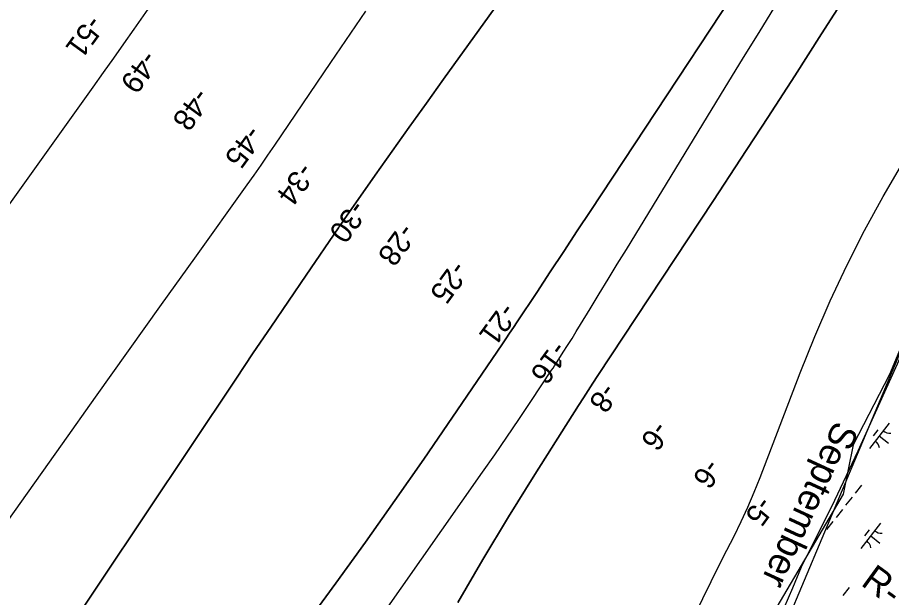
# Model space of a CAD drawing. Extents: x 3896831 to 3918110, y 171006 to 193349.
# Drawn here: x 3907446 to 3908805, y 178993 to 179895 of the extents above; entities that cross this region are included whole.
import ezdxf

# ---------------------------------------------------------------- set-up
doc = ezdxf.new("R2010")
doc.units = 0
for name, color, linetype in [('V-RIVR-EDGE', 7, 'Continuous'), ('V-RIVR-IDEN', 7, 'Continuous'), ('V-RIVR-RANG', 7, 'Continuous'), ('V-RIVR-RANG-IDEN', 7, 'Continuous'), ('V-RRAP-FSHR', 7, 'Continuous'), ('V-TOPO-DPTH', 7, 'Continuous'), ('V-TOPO-MAJR', 7, 'Continuous'), ('V-TOPO-MINR', 7, 'Continuous'), ('V-WETL-SWMP', 7, 'Continuous')]:
    doc.layers.add(name, color=color, linetype=linetype)

msp = doc.modelspace()

# ---------------------------------------------------------------- linework, layer by layer
at = {"layer": 'V-RIVR-EDGE'}
msp.add_lwpolyline([(3908875.5, 179514.5), (3908802.2, 179339.6), (3908745.8, 179230.1), (3908730, 179153.3), (3908572, 178884.7), (3908505.4, 178750.4), (3908358.7, 178539.4), (3908245.8, 178389.3), (3908234.5, 178346.4), (3908226.6, 178313.7), (3908205.2, 178288.9), (3908181.5, 178273.1), (3908140.8, 178198.6), (3908014.4, 177963.8)], dxfattribs=at)
at = {"layer": 'V-RRAP-FSHR'}
msp.add_lwpolyline([(3910095.3, 181395.6), (3909257.3, 180118.1), (3908889.4, 179541.5), (3908614.7, 178888.4), (3907991.9, 177840.9), (3908307, 176956.6)], dxfattribs=at)
at = {"layer": 'V-TOPO-DPTH'}
for points in [[(3907701.3, 178701.9), (3907713.1, 178714.3), (3907715.7, 178717), (3907732.5, 178735.7), (3907748.8, 178754.8), (3907764.5, 178774.4), (3907779.6, 178794.5), (3907940.9, 179015), (3907987.1, 179078.9), (3908032.9, 179143.2), (3908078, 179207.9), (3908122.6, 179272.9), (3908199.2, 179385.8), (3908205.2, 179394.7), (3908211.2, 179403.6), (3908217.1, 179412.5), (3908223.1, 179421.4), (3908253.4, 179467.2), (3908274.5, 179499), (3908295.6, 179530.8), (3908316.6, 179562.6), (3908337.6, 179594.5), (3908658.6, 180081.4)], [(3908658.6, 180081.4), (3908337.6, 179594.5), (3908316.6, 179562.6), (3908295.6, 179530.8), (3908274.5, 179499), (3908253.4, 179467.2), (3908223.1, 179421.4), (3908217.1, 179412.5), (3908211.2, 179403.6), (3908205.2, 179394.7), (3908199.2, 179385.8), (3908122.6, 179272.9), (3908078, 179207.9), (3908032.9, 179143.2), (3907987.1, 179078.9), (3907940.9, 179015), (3907779.6, 178794.5), (3907764.5, 178774.4), (3907748.8, 178754.8), (3907732.5, 178735.7), (3907715.7, 178717), (3907713.1, 178714.3), (3907701.3, 178701.9)], [(3907459.1, 178850.4), (3907501.4, 178908), (3907503.3, 178910.7), (3907505.2, 178913.4), (3907785.4, 179332.4), (3907812.6, 179372.9), (3907839.8, 179413.2), (3907867.2, 179453.5), (3907894.6, 179493.8), (3907945.2, 179567.6), (3907947.4, 179570.9), (3907949.7, 179574.2), (3907952, 179577.4), (3907954.2, 179580.7), (3908002.4, 179649.3), (3908028.8, 179686.8), (3908055.3, 179724.2), (3908082, 179761.6), (3908108.7, 179798.9), (3908234.7, 179974.1)], [(3908234.7, 179974.1), (3908108.7, 179798.9), (3908082, 179761.6), (3908055.3, 179724.2), (3908028.8, 179686.8), (3908002.4, 179649.3), (3907954.2, 179580.7), (3907952, 179577.4), (3907949.7, 179574.2), (3907947.4, 179570.9), (3907945.2, 179567.6), (3907894.6, 179493.8), (3907867.2, 179453.5), (3907839.8, 179413.2), (3907812.6, 179372.9), (3907785.4, 179332.4), (3907505.2, 178913.4), (3907503.3, 178910.7), (3907501.4, 178908), (3907459.1, 178850.4)], [(3908760.1, 179968.6), (3908696.6, 179869.1), (3908654.9, 179804), (3908612.9, 179739.1), (3908570.7, 179674.4), (3908528.2, 179609.8), (3908348.5, 179337.6), (3908341, 179326.1), (3908333.5, 179314.6), (3908326, 179303), (3908318.6, 179291.4), (3908250.5, 179183.8), (3908209.6, 179118.1), (3908169.5, 179051.9), (3908130.5, 178985)], [(3907386, 179049.7), (3907515.6, 179231.7), (3907567, 179304), (3907618.5, 179376.2), (3907670, 179448.4), (3907721.6, 179520.6), (3907803, 179634.3), (3907813.9, 179649.6), (3907824.6, 179665), (3907835.3, 179680.4), (3907845.9, 179695.9), (3907933.2, 179824.8), (3907987.5, 179904.7)], [(3907386, 179049.7), (3907515.6, 179231.7), (3907567, 179304), (3907618.5, 179376.2), (3907670, 179448.4), (3907721.6, 179520.6), (3907803, 179634.3), (3907813.9, 179649.6), (3907824.6, 179665), (3907835.3, 179680.4), (3907845.9, 179695.9), (3907933.2, 179824.8), (3907987.5, 179904.7)]]:
    msp.add_lwpolyline(points, dxfattribs=at)
at = {"layer": 'V-TOPO-MAJR'}
msp.add_lwpolyline([(3907384.1, 179535.8), (3907563.5, 179786.5), (3907579.5, 179809), (3907595.5, 179831.4), (3907611.3, 179853.9), (3907627.1, 179876.4), (3907935.8, 180317.5)], dxfattribs=at)
at = {"layer": 'V-TOPO-MINR'}
for points in [[(3907701.3, 178701.9), (3907713.1, 178714.3), (3907715.7, 178717), (3907732.5, 178735.7), (3907748.8, 178754.8), (3907764.5, 178774.4), (3907779.6, 178794.5), (3907940.9, 179015), (3907987.1, 179078.9), (3908032.9, 179143.2), (3908078, 179207.9), (3908122.6, 179272.9), (3908199.2, 179385.8), (3908205.2, 179394.7), (3908211.2, 179403.6), (3908217.1, 179412.5), (3908223.1, 179421.4), (3908253.4, 179467.2), (3908274.5, 179499), (3908295.6, 179530.8), (3908316.6, 179562.6), (3908337.6, 179594.5), (3908658.6, 180081.4)], [(3907459.1, 178850.4), (3907501.4, 178908), (3907503.3, 178910.7), (3907505.2, 178913.4), (3907785.4, 179332.4), (3907812.6, 179372.9), (3907839.8, 179413.2), (3907867.2, 179453.5), (3907894.6, 179493.8), (3907945.2, 179567.6), (3907947.4, 179570.9), (3907949.7, 179574.2), (3907952, 179577.4), (3907954.2, 179580.7), (3908002.4, 179649.3), (3908028.8, 179686.8), (3908055.3, 179724.2), (3908082, 179761.6), (3908108.7, 179798.9), (3908234.7, 179974.1)], [(3908130.5, 178985), (3908169.5, 179051.9), (3908209.6, 179118.1), (3908250.5, 179183.8), (3908318.6, 179291.4), (3908326, 179303), (3908333.5, 179314.6), (3908341, 179326.1), (3908348.5, 179337.6), (3908528.2, 179609.8), (3908570.7, 179674.4), (3908612.9, 179739.1), (3908654.9, 179804), (3908696.6, 179869.1), (3908760.1, 179968.6)], [(3907849.4, 178731.1), (3908169.1, 179187.3), (3908188.1, 179214.6), (3908207, 179242), (3908225.7, 179269.6), (3908244.2, 179297.3), (3908276.7, 179346.1), (3908278.9, 179349.4), (3908281.1, 179352.7), (3908283.2, 179356), (3908285.4, 179359.3), (3908294.8, 179374), (3908301.6, 179384.7), (3908308.4, 179395.4), (3908315, 179406.2), (3908321.7, 179417), (3908336.6, 179441.6), (3908350.7, 179464.7), (3908364.8, 179487.8), (3908378.8, 179510.9), (3908392.9, 179534), (3908546.7, 179785.9), (3908573.7, 179830), (3908600.8, 179874.1), (3908627.9, 179918.2)], [(3907386, 179049.7), (3907515.6, 179231.7), (3907567, 179304), (3907618.5, 179376.2), (3907670, 179448.4), (3907721.6, 179520.6), (3907803, 179634.3), (3907813.9, 179649.6), (3907824.6, 179665), (3907835.3, 179680.4), (3907845.9, 179695.9), (3907933.2, 179824.8), (3907987.5, 179904.7)], [(3908537.4, 179043.2), (3908537.8, 179044), (3908549.4, 179066), (3908560.7, 179088.2), (3908571.6, 179110.6), (3908582.1, 179133.2), (3908591.8, 179156.2), (3908601.1, 179179.3), (3908663.5, 179342.2), (3908686.1, 179398.5), (3908710.1, 179454.2), (3908735.9, 179509), (3908763.1, 179563.2), (3908792.3, 179616.4), (3908822.9, 179668.7), (3908855.6, 179719.7), (3908889.8, 179769.8), (3908950, 179854.2), (3908955.2, 179861.4), (3908960.3, 179868.6), (3908965.4, 179875.9), (3908970.5, 179883.1), (3908975.6, 179890.4), (3908980.6, 179897.7)], [(3908537.4, 179043.2), (3908434.2, 178833), (3908266.3, 178537.3), (3908184.5, 178417.7), (3908134.2, 178297.4), (3908060.4, 178111.6), (3908032.4, 177973.8), (3908028.6, 177895.2)]]:
    msp.add_lwpolyline(points, dxfattribs=at)
at = {"layer": 'V-WETL-SWMP'}
for p, q in [((3908787.7, 179296.4), (3908829.3, 179388)), ((3908753.4, 179220.8), (3908787.7, 179296.4)), ((3908801.8, 179263.6), (3908771, 179224.3)), ((3908784, 179253.4), (3908776.6, 179244)), ((3908786.4, 179243.9), (3908800.5, 179232.8)), ((3908712.3, 179134.2), (3908753.4, 179220.8)), ((3908758.7, 179167.4), (3908748.8, 179154.9)), ((3908743.9, 179148.6), (3908734, 179136)), ((3908679, 179067.4), (3908712.3, 179134.2)), ((3908729.1, 179129.7), (3908719.2, 179117.1)), ((3908714.2, 179110.8), (3908704.4, 179098.2)), ((3908788.4, 179108), (3908757.5, 179068.7)), ((3908770.6, 179097.8), (3908763.2, 179088.4)), ((3908773, 179088.4), (3908787.1, 179077.3)), ((3908665.6, 179040.4), (3908679, 179067.4)), ((3908651.7, 179007.8), (3908665.6, 179040.4)), ((3908615.5, 178924.6), (3908651.7, 179007.8)), ((3908739.7, 179008.3), (3908729.8, 178995.7))]:
    msp.add_line(p, q, dxfattribs=at)
for centre, start, end in [((3908803.6, 179265.5), 231.1403, 272.6839), ((3908769.5, 179222), 11.1403, 52.6839), ((3908790.2, 179110), 231.1403, 272.6839), ((3908756.1, 179066.5), 11.1403, 52.6839)]:
    msp.add_arc(centre, 17.6, start, end, dxfattribs=at)

# ---------------------------------------------------------------- texts
at = {"layer": 'V-RIVR-IDEN'}
msp.add_text('September', height=42, rotation=245.1683, dxfattribs=at).set_placement((3908717.6, 179269.4))
at = {"layer": 'V-RIVR-RANG'}
for s, rotation, p in [('-51', 233.9461, (3907557.1, 179900.4)), ('-49', 233.9461, (3907642.4, 179845.6)), ('-48', 233.9461, (3907723.3, 179787.3)), ('-45', 233.9461, (3907804.5, 179729)), ('-34', 233.9461, (3907885.5, 179671.3)), ('-30', 233.9461, (3907966.9, 179612.8)), ('-28', 233.8083, (3908042.9, 179576.9)), ('-25', 233.8083, (3908124, 179518.4)), ('-21', 233.8083, (3908200.3, 179453.3)), ('-16', 233.8083, (3908280.3, 179393.3)), ('-8', 233.8083, (3908356.8, 179328.5)), ('-6', 233.8083, (3908437.5, 179269.4)), ('-6', 233.8083, (3908518.3, 179210.6)), ('-5', 233.8083, (3908599.6, 179152.3))]:
    msp.add_text(s, height=33.5, rotation=rotation, dxfattribs=at).set_placement(p)
at = {"layer": 'V-RIVR-RANG-IDEN'}
msp.add_text('R-104-C', height=41.5, rotation=323.9528, dxfattribs=at).set_placement((3908756.1, 179012.7))

doc.saveas('drawing.dxf')
